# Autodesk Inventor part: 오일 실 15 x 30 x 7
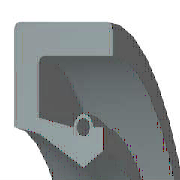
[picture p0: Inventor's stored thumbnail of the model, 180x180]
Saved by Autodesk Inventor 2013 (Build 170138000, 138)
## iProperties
Created: 2012-02
Part Number: 오일 실 15 x 30 x 7
Material: 고무
Description: 오일-실
Document SubType Name: Modeling
Standard: KS B 2804
Designer: mduedu
Standards Organization: KS
Language: ko-KR
Size Designation: S - 15 25 7
Categories: <MemberInstance><Categories><Category DisplayName="샤프트 부품" InternalName="7f7aeb1f-a693-4053-b835-cee3144e0d98" Mnemonic="SHFT"><Category DisplayName="실링" Intern
Density: 0.93 g/cm^3
IsCustomPart: 1
Author: mduedu
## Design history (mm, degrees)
revolve "본체" stored, may be unused: angle "d17" = 90 deg
revolve "스프링1" stored, may be unused: angle "d18" = 90 deg
body "Solid1"
sketch "스케치1"
  geometry: L1 (0, 15)-(7, 15); L2 (7, 15)-(7, 13.75); L3 (7, 13.75)-(1.75, 13.75); L4 (0, 15)-(0, 9.6); L5 (0, 9.6)-(1.75, 9.25); L6 (1.75, 9.25)-(4.9, 7.5); L7 (4.9, 7.5)-(0, 7.5); L8 (6.3, 8.375)-(6.3, 9.6); L9 (0, 0)-(9.586, 0) reference; L10 (4.9, 7.5)-(6.3, 8.375); L11 (0, 15)-(0, -2.5) reference; L12 (-1.917, 0)-(11.503, 0) reference; L13 (4.2, 9.6)-(1.75, 10.09); L14 (1.75, 10.09)-(1.75, 13.75); L15 (6.3, 9.6)-(5.6, 9.6); C1 r 0.455 at (4.9, 9.6); A1 r 0.7 centre (4.9, 9.6) between (5.6, 9.6) and (4.2, 9.6)
  constraints: 26 end point, 5 horizontal alignment, 4 perpendicular, 2 centre point, 2 collinear, 2 horizontal, 2 parallel, 2 point on circle, 2 point on line, 2 vertical alignment, 1 coincident
  dimensions: "d0" = 30 diameter of L1 L9 (= SD2); "d1" = 16.75 diameter of L8.start L9 (= ABDM); "d2" = 1.25 distance of L1.end L2.end (computed from SD); "d3" = 0.91 diameter of C1 (= SPDI); "d4" = 1.4 diameter of A1 (= SPDA); "d5" = 15 diameter of L6.end L9 (= NND); "d6" = 18.5 diameter of L5.end L9 (= TKDM); "d7" = 19.2 diameter of L4.end L9 (= HLDM); "d8" = 4.9 distance from line of C1.centre L4 (= SPDST); "d9" = 6.3 distance between parallel lines of L8 L4 (= SDI); "d10" = 7 distance between parallel lines of L2 L4 (= SWDT); "d12" = 1.75 distance between parallel lines of L14 L4 (= SD)
fillet "모깎기1" dims "d11" = 0.5 (= RR)
other parameters: "SD2" = 30 [user parameter; used in 1 equation term], "SWDT" = 7 [user parameter; used in 1 equation term], "RR" = 0.5 [user parameter; used in 1 equation term], "SD" = 1.75 [user parameter; used in 2 equation terms], "NND" = 15 [user parameter; used in 1 equation term], "SPDA" = 1.4 [user parameter; used in 1 equation term], "SPDI" = 0.91 [user parameter; used in 1 equation term], "TKDM" = 18.5 [user parameter; used in 1 equation term], "HLDM" = 19.2 [user parameter; used in 1 equation term], "ABDM" = 16.75 [user parameter; used in 1 equation term], "SDI" = 6.3 [user parameter; used in 1 equation term], "SPDST" = 4.9 [user parameter; used in 1 equation term], "d13" = 0, "d14" = 0, "d15" = 0, "LAB" = 0.35 [user parameter]
